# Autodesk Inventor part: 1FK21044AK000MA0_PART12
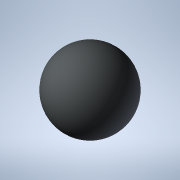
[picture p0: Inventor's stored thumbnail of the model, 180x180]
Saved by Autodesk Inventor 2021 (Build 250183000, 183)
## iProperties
Created: 2025-04
Part Number: 1FK21044AK000MA0_PART12
Material: Generic
Catalog Web Link: www.3dfindit.com
Description: -Servo synchronous motor
Document SubType Name: Modeling
Designer: psAdmin
Mass: 0.137258 g
Surface Area: 1.2868 cm^2
Volume: 0.137258 cm^3
Density: 1 g/cm^3
Appearance: PSOLRGB-212-217-219
Category: PARTsolutions
Title: 1FK21044AK000MA0_PART12
Author: Cadenas PARTsolutions
Comments: Servo synchronous motor
Sending System: PARTsolutions
Preprocessor: ST-DEVELOPER v19.3
PSOL_IDENT_0: {$CADENAS_DATA/23d-libs/siemens_ag/_cat_/87/f4/1fk21044ak000ma0.prj},216 {VTYP=3D},{NB=1FK21044AK000
PSOL_IDENT_1: MA0_PART12},{LINA=1FK21044AK000MA0_PART12},{NN=1FK21044AK000MA0_PART12},{NOPRJ=TRUE},{DATE=19.08.202
PSOL_IDENT_2: 5 14:00:48},{GEOMDATE=30.07.2025 02:00:50},{VERSION=},{LINEID=10},{WBVAR=},{WBNUMERIC=}  {NB=1FK2104
PSOL_IDENT_3: 4AK000MA0_PART12},{LINA=1FK21044AK000MA0_PART12},{KT=DUMMY},{PREVIEW=../../../_pool_/cb/72/p_d211_xx
PSOL_IDENT_4: _00434j.png},{DESCSHORT=SIMOTICS S-1FK2 HD, SINAMICS S210 3AC 400V-480V, 0.95 Nm, 6000 rpm},{DESCLON
PSOL_IDENT_5: G=SIMOTICS S-1FK2 HD servo motor M0=1.27 Nm; PN = 0.6 kW at nN=6000 rpm (380-480 V); PN = 0.4 kW at
PSOL_IDENT_6: nN=3000 rpm (200-240 V); degree of protection IP64; cylindrical shaft D19x40mm; absolute encoder 22-
PSOL_IDENT_7: bit + 12-bit multiturn (encoder AM22DQC); with OCC interface; plug size M17, rotatable; SIMOTICS S-1
PSOL_IDENT_8: FK2 servomotorfor a wide range of uses in industrial environments. SIMOTICS S‑1FK2 servomotors are c
PSOL_IDENT_9: ompact synchronous motors with a high dynamic performance that set themselves apart as a result of t
PSOL_IDENT_10: heir high power density, degree of protection and overload capability. The motors are available in t
PSOL_IDENT_11: wo variants: as High Dynamic variant (highest dynamic performance as a result of the low intrinsic m
PSOL_IDENT_12: oment of inertia for applications demanding a high dynamic performance with low moved masses) - and
PSOL_IDENT_13: as Compact variant (precise and stable closed-loop control for medium up to large moved masses as a
PSOL_IDENT_14: result of a medium intrinsic moment of inertia). SIMOTICSS‑1FK2 servomotors fully exploit their stre
PSOL_IDENT_15: ngths in a system with the SINAMICSS210 frequency converter and simple connection using the one cabl
PSOL_IDENT_16: e connection (OCC). Advantages include the short control and positioning times, fast and precise cor
PSOL_IDENT_17: rection of disturbing quantities as well as stable control with a high dynamic performance. The serv
PSOL_IDENT_18: o motors can be configured to address a wide range of requirements. For example with and without hol
PSOL_IDENT_19: ding brake, IP64 or IP65 degree of protection, singleturn or multiturn absolute encoders - to name j
PSOL_IDENT_20: ust a few. Further, the servomotors are available in different shaft heights extending from 20 to 10
PSOL_IDENT_21: 0. A shaft sealing ring is available to achieve an IP65 degree of protection and for subsequent moun
PSOL_IDENT_22: ting at the motor or as spare part. SIMOTICS - the optimum motor for each and every motion control a
PSOL_IDENT_23: pplication.},{INTNO=195125056312},{SUPPLIERALTNO=1FK2104-4AK00-0MA0},{MANUID=1FK21044AK000MA0},{MANU
PSOL_IDENT_24: NAME=Siemens},{MANUTYPEDESC=Synchronous motor 1FK2-HD 1,27 Nm},{AAU732=SIMOTICS},{AAO057=S-1FK2},{AA
PSOL_IDENT_25: U734=SIMOTICS S-1FK2 HD servo motor M0=1.27 Nm; PN = 0.6 kW at nN=6000 rpm (380-480 V); PN = 0.4 kW
PSOL_IDENT_26: at nN=3000 rpm (200-240 V); degree of protection IP64; cylindrical shaft D19x40mm; absolute encoder
PSOL_IDENT_27: 22-bit + 12-bit multiturn (encoder AM22DQC); with OCC interface; plug size M17, rotatable;},{AAW338=
PSOL_IDENT_28: Synchronous motor 1FK2-HD 1,27 Nm},{AAO742=SIMOTICS},{AAO663=4042948690994},{NOCUPEROU=1},{PRICEQUAN
PSOL_IDENT_29: TITY=1},{QUANTITYMIN=1},{QUANTITYINT=1},{CTN=85015100},{COO=DE},{AAO676=1FK2104-4AK00-0MA0},{AAO677=
PSOL_IDENT_30: Siemens AG},{ORDERUNIT=C62},{CONTENTUNIT=C62}
NB: 1FK21044AK000MA0_PART12
NT: Servo synchronous motor
NBSYN: $MANUID._PART12
LINA: 1FK21044AK000MA0_PART12
CATALOG: SIEMENS
PREVIEW: ../../../_pool_/cb/72/p_d211_xx_00434j.png
DESCSHORT: SIMOTICS S-1FK2 HD, SINAMICS S210 3AC 400V-480V, 0.95 Nm, 6000 rpm
DESCLONG: SIMOTICS S-1FK2 HD servo motor M0=1.27 Nm; PN = 0.6 kW at nN=6000 rpm (380-480 V); PN = 0.4 kW at nN=3000 rpm (200-240 V); degree of protection IP64; cylindrica
INTNO: 195125056312
SUPPLIERALTNO: 1FK2104-4AK00-0MA0
MANUID: 1FK21044AK000MA0
MANUNAME: Siemens
MANUTYPEDESC: Synchronous motor 1FK2-HD 1,27 Nm
AAU732: SIMOTICS
AAO057: S-1FK2
AAU734: SIMOTICS S-1FK2 HD servo motor M0=1.27 Nm; PN = 0.6 kW at nN=6000 rpm (380-480 V); PN = 0.4 kW at nN=3000 rpm (200-240 V); degree of protection IP64; cylindrica
AAW338: Synchronous motor 1FK2-HD 1,27 Nm
AAO742: SIMOTICS
AAO663: 4042948690994.0
NOCUPEROU: 1
PRICEQUANTITY: 1
QUANTITYMIN: 1
QUANTITYINT: 1
CTN: 85015100
COO: DE
ARTICLENO: 1FK21044AK000MA0_PART12
BOMINFO: 1FK21044AK000MA0_PART12
CREATOR: CADENAS GmbH
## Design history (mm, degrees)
feature "2025_04_17_15_37_40_0588"
body "Solid1"
